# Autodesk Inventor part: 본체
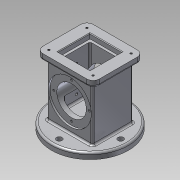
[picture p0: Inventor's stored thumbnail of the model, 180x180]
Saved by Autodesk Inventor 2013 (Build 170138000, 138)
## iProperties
Created: 2018-10
Part Number: 본체
Material: 알루미늄 6061
Document SubType Name: Modeling
Designer: hana-max6
Density: 2.40731 g/cm^3
Mass: 877.844 g
Surface Area: 743.905 cm^2
Volume: 364.657 cm^3
Author: hana-max6
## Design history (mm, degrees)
sketch "스케치1"
  geometry: C1 r 62.5 at (0, 0); 1 further point
  constraints: 1 centre point, 1 coincident
  dimensions: "d0" = 125 diameter of C1
extrude "돌출1" new body sketch "스케치1" distance "d2" = 10; taper "d3" = 0 deg
sketch "스케치2"
  geometry: L1 (-37, -33)-(37, -33); L2 (37, -33)-(37, 33); L3 (37, 33)-(-37, 33); L4 (-37, 33)-(-37, -33); L5 (-37, -33)-(37, 33); L6 (37, -33)-(-37, 33); C1 r 62.5 at (0, 0) reference
  constraints: 12 end point, 2 midpoint, 2 parallel, 1 horizontal, 1 perpendicular
  dimensions: "d4" = 74 distance of L3.end L2.end; "d5" = 66 distance of L2.end L1.end
extrude "돌출2" join sketch "스케치2" distance "d6" = 88; taper "d7" = 0 deg
sketch "스케치3"
  geometry: L1 (-46, -41)-(46, -41); L2 (46, -41)-(46, 41); L3 (46, 41)-(-46, 41); L4 (-46, 41)-(-46, -41); L5 (-46, -41)-(46, 41); L6 (46, -41)-(-46, 41); 1 further point
  constraints: 12 end point, 2 midpoint, 2 parallel, 1 horizontal, 1 perpendicular
  dimensions: "d8" = 92 distance of L3.end L2.end; "d9" = 82 distance of L2.end L1.end
extrude "돌출3" join sketch "스케치3" distance "d10" = 10; taper "d11" = 0 deg
sketch "스케치5"
  geometry: L1 (-33, 89)-(-30, 89); L2 (-30, 89)-(-30, 78); L3 (-30, 78)-(30, 78); L4 (30, 78)-(30, 89); L5 (30, 89)-(33, 89); L6 (-63.016, 54)-(67.581, 54); L7 (-62.5, 0)-(62.5, 0) reference; L8 (-33, 89)-(-33, 54); L9 (33, 89)-(33, 54); 3 further points
  constraints: 16 end point, 4 horizontal, 2 midpoint, 2 point on line, 2 vertical, 1 collinear, 1 vertical alignment
  dimensions: "d12" = 54 distance between parallel lines of L7 L6; "d13" = 70 diameter of L1 L6; "d14" = 48 diameter of L3 L6; "d17" = 3 distance between parallel lines of L4 L9; "d18" = 33 distance from line of point (0, 0) L9; "d20" = 66 distance between parallel lines of L9 L8
revolve "회전1" sketch "스케치5" stored, may be unused: angle "d21" = 90 deg
sketch "스케치6"
  geometry: C1 r 62.5 at (0, 0) reference; C2 r 28 at (0, 0)
  constraints: 1 centre point, 1 coincident
  dimensions: "d23" = 56 diameter of C2
extrude "돌출4" cut sketch "스케치6" distance "d25" = 18; taper "d26" = 0 deg
feature "면 기울기1" dims angle "d27" = 10 deg
fillet "모깎기1" dims "d28" = 3
fillet "모깎기2" dims "d29" = 3
sketch "스케치7"
  geometry: L1 (26, -26)-(-26, -26); L2 (-26, -26)-(-26, 26); L3 (-26, 26)-(26, 26); L4 (26, 26)-(26, -26); L5 (26, -26)-(-26, 26); L6 (-26, -26)-(26, 26); 1 further point
  constraints: 12 end point, 2 midpoint, 2 parallel, 1 horizontal, 1 perpendicular
  dimensions: "d30" = 52 distance of L2.end L3.end; "d31" = 52 distance of L1.end L2.end
extrude "돌출5" cut sketch "스케치7" distance "d32" = 8; taper "d33" = 0 deg
sketch "스케치8"
  geometry: L1 (-22, -22)-(22, -22); L2 (22, -22)-(22, 22); L3 (22, 22)-(-22, 22); L4 (-22, 22)-(-22, -22); L5 (-22, -22)-(22, 22); L6 (22, -22)-(-22, 22); 1 further point
  constraints: 12 end point, 2 midpoint, 2 parallel, 1 horizontal, 1 perpendicular
  dimensions: "d34" = 44 distance of L3.end L2.end; "d35" = 44 distance of L2.end L1.end
extrude "돌출6" cut sketch "스케치8" distance "d36" = 74; taper "d37" = 0 deg
chamfer "모따기1" distance "d38" = 1; stored, may be unused: second distance "d39" = 2, angle "d40" = 45 deg
fillet "모깎기3" dims "d41" = 3
fillet "모깎기4" dims "d42" = 3
fillet "모깎기5" dims "d43" = 10
fillet "모깎기6" dims "d44" = 3
fillet "모깎기7" dims "d45" = 3
fillet "모깎기8" dims "d46" = 3
sketch "스케치9" dims "d48" = 58
  geometry: C1 r 24 at (0, 0) reference; C2 r 35 at (0, 0) reference; 3 further points
  constraints: 2 vertical alignment, 1 coincident, 2 other
hole "구멍1" sketch "스케치9" at (0, 29) diameter "d50" = 3.242; stored, may be unused: countersink angle "d54" = 90 deg, drill point angle "d56" = 118 deg; dims "d51" = 4, "d52" = 4, "d53" = 2, "d55" = 6
sketch "스케치10"
  geometry: A1 r 10 centre (-36, 31) between (-36, 41) and (-46, 31) reference; A2 r 10 centre (-36, -31) between (-46, -31) and (-36, -41) reference; A3 r 10 centre (36, -31) between (36, -41) and (46, -31) reference; A4 r 10 centre (36, 31) between (46, 31) and (36, 41) reference; 1 further point
hole "구멍2" sketch "스케치10" at (-36, -31), (36, -31), (36, 31), (-36, 31) diameter "d60" = 3.242; stored, may be unused: countersink angle "d64" = 90 deg, drill point angle "d66" = 118 deg; dims "d61" = 4, "d62" = 4, "d63" = 2, "d65" = 6
sketch "스케치11" dims "d68" = 100
  geometry: C1 r 59.5 at (0, 0) reference; 2 further points
  constraints: 2 vertical alignment, 1 coincident, 2 other
hole "구멍3" sketch "스케치11" at (0, 50) diameter "d70" = 9; stored, may be unused: countersink angle "d74" = 90 deg, drill point angle "d76" = 118 deg; dims "d71" = 4, "d72" = 4, "d73" = 2, "d75" = 6
sketch "스케치12"
  geometry: L1 (0, 60)-(0, 0) reference; L2 (-82, 0)-(-82, 60) reference; L3 (-82, 30)-(0, 30); L4 (-95, 92.5)-(-95, -32.5) reference; 3 further points
  constraints: 2 end point, 2 midpoint, 2 point on line
  dimensions: "d80" = 37 distance from line of L4 point (-58, 30); "d81" = 43 distance of point (-58, 30) point (-15, 30)
hole "구멍4" sketch "스케치12" at (-58, 30), (-15, 30) diameter "d82" = 4.134; stored, may be unused: countersink angle "d86" = 90 deg, drill point angle "d88" = 118 deg; dims "d83" = 4, "d84" = 4, "d85" = 2, "d87" = 50
sketch "스케치13"
  geometry: L1 (72, 0)-(0, 0) reference; L2 (82, 0)-(82, 7) reference; 2 further points
  constraints: 1 other
  dimensions: "d89" = 4 distance from line of point (36, 4) L1; "d90" = 46 distance from line of L2 point (36, 4)
feature "엠보싱1" sketch "스케치13" dims "d3" = 0, "d11" = 0, "d91" = 0.5, "d92" = 0
node "솔리드1"
pattern_circular "원형 패턴1" dims angle "d58" = 360 deg
mirror "대칭1"
pattern_circular "원형 패턴2" dims angle "d78" = 360 deg
